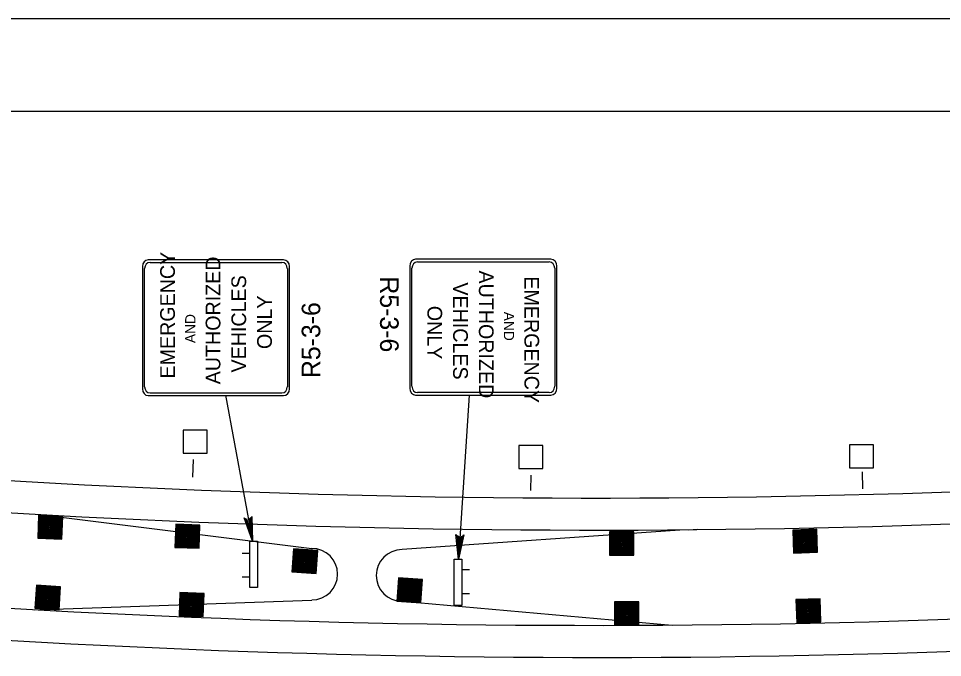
# Model space of a CAD drawing. Extents: x 640253 to 641999, y 298458 to 299646.
# Drawn here: x 641231 to 641380.3, y 299542.3 to 299645.6 of the extents above; entities that cross this region are included whole.
import ezdxf

# ---------------------------------------------------------------- set-up
doc = ezdxf.new("R2010")
doc.units = 0
for name, color, linetype in [('1', 7, 'Continuous'), ('2', 7, 'Continuous'), ('PLT-BNDY', 7, 'Continuous')]:
    doc.layers.add(name, color=color, linetype=linetype)

msp = doc.modelspace()

# ---------------------------------------------------------------- linework, layer by layer
at = {"layer": '1'}
msp.add_line((641134.31, 299630.63), (641920.31, 299630.63), dxfattribs=at)
at = {"layer": '2'}
for p, q in [((641273.81, 299606.6), (641251.94, 299606.6)), ((641317.01, 299606.68), (641295.14, 299606.68)), ((641250.99, 299605.5), (641250.99, 299585.75)), ((641251.34, 299586.08), (641251.34, 299605.18)), ((641252.22, 299606.19), (641273.53, 299606.19)), ((641274.41, 299605.18), (641274.41, 299586.08)), ((641274.77, 299585.75), (641274.77, 299605.5)), ((641294.19, 299605.58), (641294.19, 299585.83)), ((641294.54, 299586.15), (641294.54, 299605.26)), ((641295.42, 299606.27), (641316.73, 299606.27)), ((641317.61, 299605.26), (641317.61, 299586.15)), ((641317.96, 299585.83), (641317.96, 299605.58)), ((641251.94, 299584.66), (641273.81, 299584.66)), ((641273.53, 299585.06), (641252.22, 299585.06)), ((641295.14, 299584.73), (641317.01, 299584.73)), ((641316.73, 299585.14), (641295.42, 299585.14)), ((641259.12, 299571.43), (641259.24, 299574.31)), ((641367.39, 299569.57), (641367.33, 299572.3)), ((641313.76, 299569.29), (641313.78, 299571.77)), ((641234.43, 299565.41), (641278.36, 299559.94)), ((641292.94, 299559.81), (641337.84, 299562.94)), ((641339.24, 299562.96), (641340.74, 299563.06)), ((641268.37, 299559.11), (641267.12, 299559.11)), ((641302.59, 299556.51), (641303.84, 299556.51)), ((641268.37, 299555.26), (641267.12, 299555.26)), ((641302.59, 299552.66), (641303.84, 299552.66)), ((641233.6, 299550.02), (641278.36, 299551.58)), ((641292.94, 299551.4), (641336.58, 299547.52))]:
    msp.add_line(p, q, dxfattribs=at)
for points in [[(641264.39, 299584.73), (641268.78, 299561.09)], [(641303.8, 299584.73), (641302.04, 299558.18)], [(641234.08, 299561.57), (641237.98, 299561.43), (641238.11, 299565.17), (641234.22, 299565.31), (641234.08, 299561.57), (641238.05, 299565.11), (641234.28, 299565.24), (641234.15, 299561.62), (641237.92, 299561.48), (641238.05, 299565.04), (641234.36, 299565.17), (641234.23, 299561.68), (641237.84, 299561.56), (641237.95, 299564.96), (641234.42, 299565.08), (641234.3, 299561.74), (641237.78, 299561.62), (641237.9, 299564.9), (641234.48, 299565.02), (641234.37, 299561.79), (641237.7, 299561.68), (641237.81, 299564.83), (641234.55, 299564.95), (641234.43, 299561.85), (641237.64, 299561.76), (641237.72, 299564.76), (641234.62, 299564.87), (641234.5, 299561.91), (641237.57, 299561.83), (641237.66, 299564.7), (641234.68, 299564.8), (641234.56, 299561.99), (641237.49, 299561.91), (641237.58, 299564.61), (641234.77, 299564.72), (641234.64, 299562.04), (641237.39, 299561.99), (641237.49, 299564.55), (641234.84, 299564.65), (641234.71, 299562.1), (641237.32, 299562.05), (641237.4, 299564.5), (641234.92, 299564.57), (641234.8, 299562.14), (641237.23, 299562.12), (641237.3, 299564.42), (641235, 299564.47), (641234.92, 299563.37), (641234.88, 299562.21), (641237.16, 299562.2), (641237.2, 299564.33), (641235.08, 299564.36), (641234.96, 299562.28), (641237.07, 299562.28), (641237.11, 299564.26), (641235.18, 299564.26), (641235.08, 299562.36), (641236.95, 299562.35), (641236.99, 299564.13), (641235.31, 299564.15), (641235.2, 299562.48), (641236.81, 299562.46), (641236.84, 299564.03), (641235.46, 299564.02), (641235.34, 299562.6), (641235.35, 299562.6), (641236.66, 299562.6), (641236.7, 299563.89), (641235.59, 299563.89), (641235.49, 299562.72), (641236.51, 299562.74), (641236.56, 299563.74), (641235.73, 299563.75), (641235.66, 299562.87), (641236.36, 299562.87), (641236.36, 299563.62), (641235.89, 299563.6), (641235.85, 299563), (641236.19, 299563.02), (641236.21, 299563.47), (641236.06, 299563.5), (641236.03, 299563.14)], [(641268.55, 299564.9), (641268.32, 299564.71), (641268.78, 299561.09), (641268.55, 299564.9), (641268.68, 299565.11), (641268.78, 299561.09), (641267.94, 299564.63), (641267.65, 299564.71), (641268.78, 299561.09), (641267.43, 299564.88), (641267.65, 299564.71)], [(641256.24, 299560.1), (641260.14, 299559.96), (641260.27, 299563.7), (641256.37, 299563.84), (641256.24, 299560.1), (641260.2, 299563.63), (641256.44, 299563.77), (641256.31, 299560.14), (641260.08, 299560.01), (641260.2, 299563.57), (641256.51, 299563.7), (641256.38, 299560.21), (641260, 299560.08), (641260.11, 299563.48), (641256.57, 299563.61), (641256.46, 299560.27), (641259.93, 299560.14), (641260.05, 299563.43), (641256.64, 299563.55), (641256.53, 299560.32), (641259.86, 299560.21), (641259.96, 299563.36), (641256.71, 299563.47), (641256.59, 299560.38), (641259.79, 299560.29), (641259.88, 299563.29), (641256.77, 299563.4), (641256.66, 299560.44), (641259.73, 299560.35), (641259.81, 299563.22), (641256.83, 299563.33), (641256.72, 299560.52), (641259.64, 299560.44), (641259.74, 299563.14), (641256.92, 299563.24), (641256.79, 299560.56), (641259.55, 299560.52), (641259.65, 299563.08), (641257, 299563.17), (641256.87, 299560.63), (641259.47, 299560.58), (641259.56, 299563.02), (641257.07, 299563.09), (641256.95, 299560.67), (641259.38, 299560.65), (641259.46, 299562.95), (641257.16, 299563), (641257.07, 299561.9), (641257.03, 299560.74), (641259.31, 299560.73), (641259.36, 299562.86), (641257.23, 299562.89), (641257.12, 299560.81), (641259.23, 299560.8), (641259.27, 299562.78), (641257.33, 299562.79), (641257.23, 299560.89), (641259.1, 299560.87), (641259.15, 299562.66), (641257.47, 299562.68), (641257.35, 299561.01), (641258.96, 299560.99), (641258.99, 299562.56), (641257.62, 299562.55), (641257.49, 299561.12), (641257.5, 299561.12), (641258.82, 299561.13), (641258.85, 299562.41), (641257.75, 299562.41), (641257.64, 299561.25), (641258.67, 299561.27), (641258.71, 299562.26), (641257.88, 299562.27), (641257.81, 299561.4), (641258.52, 299561.4), (641258.51, 299562.14), (641258.05, 299562.13), (641258.01, 299561.53), (641258.34, 299561.55), (641258.36, 299561.99), (641258.22, 299562.03), (641258.18, 299561.67)], [(641302.76, 299561.93), (641302.47, 299561.81), (641302.04, 299558.18), (641302.76, 299561.93), (641302.93, 299562.1), (641302.04, 299558.18), (641302.1, 299561.83), (641301.83, 299561.97), (641302.04, 299558.18), (641301.66, 299562.2), (641301.83, 299561.97)], [(641326.48, 299558.84), (641330.38, 299558.84), (641330.38, 299562.59), (641326.48, 299562.59), (641326.48, 299558.84), (641330.32, 299562.52), (641326.55, 299562.52), (641326.55, 299558.89), (641330.32, 299558.89), (641330.32, 299562.45), (641326.62, 299562.45), (641326.62, 299558.96), (641330.24, 299558.96), (641330.23, 299562.36), (641326.69, 299562.36), (641326.69, 299559.02), (641330.17, 299559.02), (641330.17, 299562.3), (641326.76, 299562.3), (641326.76, 299559.08), (641330.09, 299559.09), (641330.08, 299562.24), (641326.83, 299562.24), (641326.82, 299559.14), (641330.03, 299559.16), (641330.01, 299562.16), (641326.9, 299562.16), (641326.89, 299559.2), (641329.96, 299559.22), (641329.94, 299562.09), (641326.96, 299562.09), (641326.95, 299559.28), (641329.87, 299559.3), (641329.87, 299562), (641327.05, 299562.01), (641327.01, 299559.33), (641329.77, 299559.38), (641329.78, 299561.94), (641327.13, 299561.94), (641327.09, 299559.4), (641329.69, 299559.44), (641329.69, 299561.89), (641327.21, 299561.87), (641327.17, 299559.44), (641329.6, 299559.51), (641329.6, 299561.81), (641327.3, 299561.78), (641327.25, 299560.68), (641327.25, 299559.51), (641329.53, 299559.59), (641329.5, 299561.71), (641327.37, 299561.67), (641327.33, 299559.59), (641329.44, 299559.65), (641329.41, 299561.63), (641327.48, 299561.57), (641327.44, 299559.67), (641329.31, 299559.72), (641329.3, 299561.5), (641327.62, 299561.47), (641327.56, 299559.8), (641329.17, 299559.83), (641329.15, 299561.4), (641327.77, 299561.34), (641327.7, 299559.91), (641327.71, 299559.91), (641329.02, 299559.97), (641329.01, 299561.25), (641327.91, 299561.21), (641327.84, 299560.05), (641328.86, 299560.1), (641328.87, 299561.1), (641328.05, 299561.08), (641328.01, 299560.2), (641328.71, 299560.23), (641328.68, 299560.97), (641328.21, 299560.94), (641328.19, 299560.34), (641328.53, 299560.37), (641328.53, 299560.81), (641328.39, 299560.84), (641328.37, 299560.48)], [(641356.19, 299559.16), (641360.08, 299559.3), (641359.96, 299563.04), (641356.06, 299562.9), (641356.19, 299559.16), (641359.9, 299562.97), (641356.13, 299562.84), (641356.25, 299559.21), (641360.02, 299559.34), (641359.9, 299562.9), (641356.21, 299562.77), (641356.33, 299559.28), (641359.94, 299559.41), (641359.81, 299562.81), (641356.28, 299562.68), (641356.39, 299559.34), (641359.87, 299559.47), (641359.76, 299562.75), (641356.35, 299562.63), (641356.46, 299559.41), (641359.79, 299559.53), (641359.67, 299562.68), (641356.42, 299562.56), (641356.52, 299559.47), (641359.72, 299559.6), (641359.59, 299562.6), (641356.49, 299562.49), (641356.58, 299559.54), (641359.65, 299559.66), (641359.53, 299562.53), (641356.56, 299562.42), (641356.64, 299559.62), (641359.56, 299559.74), (641359.47, 299562.44), (641356.65, 299562.35), (641356.71, 299559.67), (641359.46, 299559.81), (641359.38, 299562.37), (641356.73, 299562.28), (641356.78, 299559.74), (641359.38, 299559.87), (641359.29, 299562.31), (641356.81, 299562.21), (641356.86, 299559.78), (641359.29, 299559.93), (641359.2, 299562.23), (641356.9, 299562.12), (641356.89, 299561.02), (641356.93, 299559.85), (641359.21, 299560.01), (641359.11, 299562.13), (641356.98, 299562.02), (641357.02, 299559.93), (641359.12, 299560.07), (641359.02, 299562.05), (641357.09, 299561.92), (641357.12, 299560.02), (641358.99, 299560.14), (641358.91, 299561.92), (641357.23, 299561.82), (641357.23, 299560.15), (641358.84, 299560.24), (641358.77, 299561.81), (641357.39, 299561.7), (641357.37, 299560.27), (641357.38, 299560.27), (641358.69, 299560.37), (641358.63, 299561.66), (641357.53, 299561.58), (641357.51, 299560.41), (641358.53, 299560.5), (641358.5, 299561.49), (641357.68, 299561.45), (641357.67, 299560.57), (641358.37, 299560.62), (641358.31, 299561.36), (641357.85, 299561.32), (641357.85, 299560.71), (641358.19, 299560.75), (641358.17, 299561.2), (641358.03, 299561.22), (641358.02, 299560.86)], [(641275.16, 299556.14), (641279.05, 299555.86), (641279.31, 299559.6), (641275.42, 299559.87), (641275.16, 299556.14), (641279.24, 299559.53), (641275.48, 299559.8), (641275.23, 299556.18), (641278.99, 299555.92), (641279.24, 299559.46), (641275.55, 299559.72), (641275.31, 299556.24), (641278.92, 299555.99), (641279.15, 299559.38), (641275.62, 299559.63), (641275.38, 299556.29), (641278.85, 299556.05), (641279.08, 299559.33), (641275.68, 299559.57), (641275.46, 299556.35), (641278.78, 299556.12), (641278.99, 299559.26), (641275.74, 299559.49), (641275.52, 299556.4), (641278.72, 299556.2), (641278.91, 299559.2), (641275.81, 299559.41), (641275.59, 299556.47), (641278.65, 299556.27), (641278.84, 299559.13), (641275.87, 299559.34), (641275.65, 299556.54), (641278.57, 299556.36), (641278.76, 299559.05), (641275.95, 299559.25), (641275.73, 299556.58), (641278.48, 299556.44), (641278.67, 299559), (641276.02, 299559.18), (641275.81, 299556.65), (641278.41, 299556.5), (641278.58, 299558.94), (641276.09, 299559.1), (641275.89, 299556.68), (641278.32, 299556.58), (641278.47, 299558.87), (641276.18, 299559), (641276.05, 299557.91), (641275.97, 299556.74), (641278.25, 299556.66), (641278.37, 299558.78), (641276.25, 299558.89), (641276.06, 299556.81), (641278.17, 299556.74), (641278.28, 299558.71), (641276.35, 299558.79), (641276.18, 299556.89), (641278.05, 299556.81), (641278.15, 299558.59), (641276.48, 299558.67), (641276.3, 299557.01), (641277.91, 299556.93), (641278, 299558.5), (641276.62, 299558.53), (641276.45, 299557.12), (641276.46, 299557.12), (641277.77, 299557.07), (641277.85, 299558.36), (641276.75, 299558.4), (641276.6, 299557.24), (641277.62, 299557.22), (641277.71, 299558.21), (641276.88, 299558.26), (641276.78, 299557.38), (641277.48, 299557.36), (641277.5, 299558.1), (641277.03, 299558.1), (641276.97, 299557.51), (641277.31, 299557.51), (641277.34, 299557.96), (641277.2, 299558), (641277.16, 299557.64)], [(641292.09, 299551.42), (641295.98, 299551.15), (641296.24, 299554.89), (641292.35, 299555.16), (641292.09, 299551.42), (641296.17, 299554.82), (641292.41, 299555.09), (641292.16, 299551.47), (641295.92, 299551.21), (641296.16, 299554.76), (641292.48, 299555.01), (641292.24, 299551.53), (641295.84, 299551.28), (641296.07, 299554.67), (641292.54, 299554.92), (641292.31, 299551.59), (641295.78, 299551.35), (641296.01, 299554.62), (641292.61, 299554.86), (641292.38, 299551.64), (641295.71, 299551.42), (641295.92, 299554.56), (641292.67, 299554.79), (641292.45, 299551.7), (641295.64, 299551.49), (641295.83, 299554.49), (641292.73, 299554.71), (641292.52, 299551.76), (641295.58, 299551.56), (641295.76, 299554.42), (641292.8, 299554.63), (641292.58, 299551.83), (641295.5, 299551.65), (641295.69, 299554.34), (641292.88, 299554.55), (641292.65, 299551.87), (641295.41, 299551.73), (641295.59, 299554.29), (641292.95, 299554.47), (641292.73, 299551.94), (641295.33, 299551.79), (641295.5, 299554.24), (641293.02, 299554.39), (641292.82, 299551.97), (641295.25, 299551.87), (641295.4, 299554.16), (641293.11, 299554.29), (641292.98, 299553.2), (641292.9, 299552.03), (641295.18, 299551.95), (641295.3, 299554.07), (641293.17, 299554.19), (641292.99, 299552.11), (641295.09, 299552.02), (641295.2, 299554), (641293.27, 299554.08), (641293.1, 299552.19), (641294.97, 299552.1), (641295.08, 299553.89), (641293.4, 299553.96), (641293.23, 299552.3), (641294.83, 299552.22), (641294.92, 299553.79), (641293.55, 299553.82), (641293.37, 299552.41), (641293.38, 299552.41), (641294.7, 299552.37), (641294.78, 299553.65), (641293.68, 299553.69), (641293.53, 299552.53), (641294.55, 299552.51), (641294.63, 299553.51), (641293.81, 299553.55), (641293.7, 299552.67), (641294.4, 299552.65), (641294.43, 299553.39), (641293.96, 299553.4), (641293.9, 299552.79), (641294.24, 299552.8), (641294.27, 299553.25), (641294.13, 299553.29), (641294.08, 299552.93)], [(641233.63, 299550.26), (641237.52, 299549.99), (641237.78, 299553.72), (641233.89, 299554), (641233.63, 299550.26), (641237.72, 299553.66), (641233.96, 299553.92), (641233.7, 299550.31), (641237.46, 299550.04), (641237.71, 299553.6), (641234.03, 299553.85), (641233.78, 299550.37), (641237.39, 299550.12), (641237.62, 299553.51), (641234.09, 299553.76), (641233.85, 299550.42), (641237.33, 299550.18), (641237.56, 299553.46), (641234.15, 299553.7), (641233.93, 299550.48), (641237.26, 299550.25), (641237.46, 299553.4), (641234.22, 299553.62), (641233.99, 299550.53), (641237.19, 299550.33), (641237.38, 299553.33), (641234.28, 299553.55), (641234.06, 299550.6), (641237.13, 299550.4), (641237.31, 299553.26), (641234.34, 299553.47), (641234.13, 299550.67), (641237.05, 299550.49), (641237.23, 299553.18), (641234.42, 299553.39), (641234.2, 299550.71), (641236.95, 299550.57), (641237.14, 299553.13), (641234.5, 299553.31), (641234.28, 299550.77), (641236.88, 299550.63), (641237.05, 299553.07), (641234.57, 299553.23), (641234.36, 299550.81), (641236.8, 299550.71), (641236.95, 299553.01), (641234.65, 299553.13), (641234.52, 299552.04), (641234.44, 299550.87), (641236.72, 299550.79), (641236.84, 299552.91), (641234.72, 299553.02), (641234.54, 299550.94), (641236.64, 299550.86), (641236.75, 299552.84), (641234.82, 299552.92), (641234.65, 299551.02), (641236.52, 299550.94), (641236.62, 299552.72), (641234.95, 299552.8), (641234.77, 299551.14), (641236.38, 299551.06), (641236.47, 299552.63), (641235.09, 299552.66), (641234.92, 299551.25), (641234.93, 299551.25), (641236.25, 299551.21), (641236.32, 299552.49), (641235.22, 299552.53), (641235.07, 299551.37), (641236.1, 299551.35), (641236.18, 299552.35), (641235.35, 299552.38), (641235.25, 299551.51), (641235.95, 299551.49), (641235.98, 299552.23), (641235.51, 299552.24), (641235.45, 299551.64), (641235.79, 299551.64), (641235.82, 299552.09), (641235.67, 299552.12), (641235.63, 299551.77)], [(641256.92, 299549.05), (641260.82, 299548.91), (641260.95, 299552.65), (641257.05, 299552.79), (641256.92, 299549.05), (641260.88, 299552.59), (641257.12, 299552.71), (641256.99, 299549.09), (641260.76, 299548.96), (641260.88, 299552.52), (641257.19, 299552.65), (641257.07, 299549.16), (641260.68, 299549.03), (641260.79, 299552.43), (641257.25, 299552.55), (641257.14, 299549.21), (641260.61, 299549.09), (641260.73, 299552.38), (641257.32, 299552.49), (641257.21, 299549.27), (641260.54, 299549.16), (641260.64, 299552.31), (641257.39, 299552.42), (641257.27, 299549.33), (641260.47, 299549.23), (641260.56, 299552.24), (641257.45, 299552.35), (641257.34, 299549.39), (641260.41, 299549.3), (641260.49, 299552.17), (641257.51, 299552.27), (641257.4, 299549.47), (641260.32, 299549.39), (641260.42, 299552.09), (641257.6, 299552.19), (641257.47, 299549.51), (641260.23, 299549.47), (641260.32, 299552.03), (641257.68, 299552.12), (641257.55, 299549.58), (641260.15, 299549.53), (641260.24, 299551.97), (641257.75, 299552.04), (641257.63, 299549.62), (641260.06, 299549.6), (641260.14, 299551.9), (641257.84, 299551.95), (641257.75, 299550.85), (641257.71, 299549.68), (641259.99, 299549.68), (641260.03, 299551.81), (641257.91, 299551.84), (641257.8, 299549.76), (641259.91, 299549.75), (641259.95, 299551.73), (641258.01, 299551.74), (641257.91, 299549.84), (641259.78, 299549.82), (641259.82, 299551.61), (641258.15, 299551.63), (641258.03, 299549.96), (641259.64, 299549.94), (641259.67, 299551.5), (641258.3, 299551.49), (641258.17, 299550.07), (641258.18, 299550.07), (641259.5, 299550.08), (641259.53, 299551.37), (641258.43, 299551.36), (641258.32, 299550.2), (641259.34, 299550.22), (641259.39, 299551.21), (641258.56, 299551.22), (641258.49, 299550.35), (641259.2, 299550.35), (641259.19, 299551.09), (641258.73, 299551.08), (641258.68, 299550.48), (641259.02, 299550.5), (641259.04, 299550.94), (641258.9, 299550.97), (641258.86, 299550.62)], [(641327.29, 299547.54), (641331.19, 299547.54), (641331.19, 299551.29), (641327.29, 299551.29), (641327.29, 299547.54), (641331.13, 299551.21), (641327.36, 299551.21), (641327.36, 299547.59), (641331.13, 299547.59), (641331.13, 299551.15), (641327.43, 299551.15), (641327.43, 299547.66), (641331.05, 299547.66), (641331.04, 299551.06), (641327.5, 299551.06), (641327.5, 299547.72), (641330.98, 299547.72), (641330.98, 299551), (641327.57, 299551), (641327.57, 299547.77), (641330.91, 299547.79), (641330.9, 299550.93), (641327.64, 299550.93), (641327.63, 299547.84), (641330.84, 299547.85), (641330.82, 299550.86), (641327.71, 299550.86), (641327.7, 299547.9), (641330.77, 299547.92), (641330.75, 299550.79), (641327.78, 299550.79), (641327.76, 299547.98), (641330.68, 299548), (641330.68, 299550.7), (641327.86, 299550.71), (641327.82, 299548.03), (641330.58, 299548.08), (641330.59, 299550.64), (641327.94, 299550.64), (641327.9, 299548.1), (641330.51, 299548.14), (641330.51, 299550.58), (641328.02, 299550.56), (641327.98, 299548.14), (641330.42, 299548.2), (641330.41, 299550.51), (641328.11, 299550.47), (641328.06, 299549.37), (641328.06, 299548.2), (641330.34, 299548.28), (641330.31, 299550.41), (641328.19, 299550.37), (641328.15, 299548.28), (641330.25, 299548.35), (641330.22, 299550.33), (641328.29, 299550.27), (641328.26, 299548.37), (641330.12, 299548.42), (641330.11, 299550.2), (641328.43, 299550.16), (641328.37, 299548.5), (641329.98, 299548.52), (641329.96, 299550.1), (641328.58, 299550.04), (641328.51, 299548.61), (641328.52, 299548.61), (641329.83, 299548.66), (641329.82, 299549.95), (641328.72, 299549.91), (641328.65, 299548.74), (641329.68, 299548.8), (641329.68, 299549.79), (641328.86, 299549.77), (641328.82, 299548.9), (641329.52, 299548.92), (641329.49, 299549.67), (641329.03, 299549.64), (641329.01, 299549.03), (641329.34, 299549.06), (641329.34, 299549.51), (641329.2, 299549.54), (641329.18, 299549.18)], [(641356.71, 299547.91), (641360.61, 299548.05), (641360.48, 299551.79), (641356.58, 299551.65), (641356.71, 299547.91), (641360.42, 299551.72), (641356.65, 299551.59), (641356.78, 299547.96), (641360.55, 299548.1), (641360.42, 299551.65), (641356.73, 299551.52), (641356.85, 299548.04), (641360.46, 299548.16), (641360.34, 299551.56), (641356.8, 299551.44), (641356.92, 299548.1), (641360.39, 299548.21), (641360.28, 299551.5), (641356.87, 299551.38), (641356.98, 299548.16), (641360.32, 299548.28), (641360.19, 299551.43), (641356.94, 299551.31), (641357.04, 299548.21), (641360.24, 299548.35), (641360.12, 299551.35), (641357.01, 299551.24), (641357.11, 299548.29), (641360.17, 299548.41), (641360.06, 299551.28), (641357.08, 299551.17), (641357.16, 299548.37), (641360.08, 299548.49), (641359.99, 299551.19), (641357.17, 299551.1), (641357.23, 299548.42), (641359.98, 299548.56), (641359.9, 299551.12), (641357.25, 299551.03), (641357.3, 299548.49), (641359.9, 299548.62), (641359.82, 299551.06), (641357.33, 299550.96), (641357.38, 299548.53), (641359.81, 299548.68), (641359.72, 299550.98), (641357.43, 299550.87), (641357.41, 299549.77), (641357.46, 299548.6), (641359.73, 299548.76), (641359.63, 299550.88), (641357.51, 299550.77), (641357.54, 299548.68), (641359.64, 299548.82), (641359.55, 299550.8), (641357.62, 299550.67), (641357.65, 299548.77), (641359.51, 299548.89), (641359.43, 299550.67), (641357.76, 299550.57), (641357.76, 299548.9), (641359.36, 299548.99), (641359.29, 299550.56), (641357.92, 299550.45), (641357.89, 299549.02), (641357.9, 299549.02), (641359.21, 299549.12), (641359.16, 299550.41), (641358.06, 299550.33), (641358.03, 299549.16), (641359.05, 299549.25), (641359.03, 299550.25), (641358.2, 299550.2), (641358.19, 299549.32), (641358.89, 299549.37), (641358.84, 299550.11), (641358.37, 299550.07), (641358.37, 299549.46), (641358.71, 299549.5), (641358.7, 299549.95), (641358.55, 299549.97), (641358.54, 299549.61)]]:
    msp.add_lwpolyline(points, dxfattribs=at)
for points in [[(641257.58, 299575.31), (641261.48, 299575.31), (641261.48, 299579.06), (641257.58, 299579.06)], [(641311.81, 299572.84), (641315.7, 299572.84), (641315.7, 299576.58), (641311.81, 299576.58)], [(641365.22, 299572.95), (641369.11, 299572.95), (641369.11, 299576.7), (641365.22, 299576.7)], [(641268.35, 299553.59), (641268.35, 299561.09), (641269.6, 299561.09), (641269.6, 299553.59)], [(641301.37, 299550.68), (641301.37, 299558.18), (641302.62, 299558.18), (641302.62, 299550.68)]]:
    msp.add_lwpolyline(points, close=True, dxfattribs=at)
for centre, radius, start, end in [((641324.62, 301181.29), 1613.21, 264.03084, 274.7698), ((641324.62, 301181.29), 1618.4, 264.02808, 274.75447), ((641278.36, 299555.77), 4.17, 270, 90), ((641292.94, 299555.56), 4.17, 90, 270), ((641324.62, 301181.29), 1633.8, 264.01999, 274.70955), ((641324.62, 301181.29), 1638.99, 264.0173, 274.6946)]:
    msp.add_arc(centre, radius, start, end, dxfattribs=at)
for centre, major_axis, start_param, end_param in [((641251.94, 299605.5), (0, -1.1), 3.141593, 4.712389), ((641273.81, 299605.5), (0, 1.1), 4.712389, 6.283185), ((641295.14, 299605.58), (0, -1.1), 3.141593, 4.712389), ((641317.01, 299605.58), (0, 1.1), 4.712389, 6.283185), ((641252.22, 299605.18), (0, -1.01), 3.141593, 4.712389), ((641273.53, 299605.18), (0, 1.01), 4.712389, 6.283185), ((641295.42, 299605.25), (0, -1.01), 3.141593, 4.712389), ((641316.73, 299605.25), (0, 1.01), 4.712389, 6.283185), ((641251.94, 299585.75), (0, -1.1), 4.712389, 6.283185), ((641252.22, 299586.08), (0, -1.01), 4.712389, 6.283185), ((641273.53, 299586.08), (0, 1.01), 3.141593, 4.712389), ((641273.81, 299585.75), (0, 1.1), 3.141593, 4.712389), ((641295.14, 299585.83), (0, -1.1), 4.712389, 6.283185), ((641295.42, 299586.15), (0, -1.01), 4.712389, 6.283185), ((641316.73, 299586.15), (0, 1.01), 3.141593, 4.712389), ((641317.01, 299585.83), (0, 1.1), 3.141593, 4.712389)]:
    msp.add_ellipse(centre, major_axis=major_axis, ratio=0.866667, start_param=start_param, end_param=end_param, dxfattribs=at)
at = {"layer": 'PLT-BNDY'}
msp.add_lwpolyline([(641094.31, 299645.63), (641935.31, 299645.63), (641935.31, 299051.63), (641094.31, 299051.63)], close=True, dxfattribs=at)

# ---------------------------------------------------------------- texts
at = {"layer": '2'}
for s, height, rotation, p in [('EMERGENCY', 2.377, 90, (641256.24, 299587.41)), ('AUTHORIZED', 2.377, 90, (641263.59, 299586.47)), ('VEHICLES', 2.377, 90, (641267.75, 299588.38)), ('R5-3-6', 3, 270, (641289.39, 299603.91)), ('AUTHORIZED', 2.377, 270, (641305.36, 299604.87)), ('EMERGENCY', 2.377, 270, (641312.71, 299603.92)), ('VEHICLES', 2.377, 270, (641301.2, 299602.95)), ('ONLY', 2.377, 90, (641271.91, 299592.17)), ('R5-3-6', 3, 90, (641279.73, 299587.48)), ('ONLY', 2.377, 270, (641297.04, 299599.16)), ('AND', 1.664, 90, (641259.56, 299593.13)), ('AND', 1.664, 270, (641309.39, 299598.2))]:
    msp.add_text(s, height=height, rotation=rotation, dxfattribs=at).set_placement(p)

doc.saveas('drawing.dxf')
